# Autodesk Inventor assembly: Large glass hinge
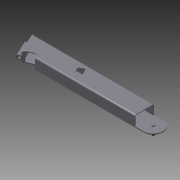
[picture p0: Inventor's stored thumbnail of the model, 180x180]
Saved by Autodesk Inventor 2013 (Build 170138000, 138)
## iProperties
Shininess: 64.0
Length Units: 11269
Angle Units: 11279
Time Units: 11290
Mass Units: 11283
Length Display Precision: 3
Angle Display Precision: 2
Compacted: True
Created: 2005-02
Part Number: Large glass hinge
Document SubType Name: Assembly
Designer: =<Author>
Manufacturer: Standard
Standards Organization: Custom
Description: =<Part Number>
Density: 0.0
Volumn: 0.0
Area: 0.0
PropertySet Name: Model Information
Control State: 0
Master: False
Checked Out: False
Checked Out Date: 2008-10-15
Last Check In Date: 2008-10-15
Author: PVitaliy
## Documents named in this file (6)
- Y:\Dropbox\Launch 2013\Eco Material Advisor\Assy, Door\_Data\Assy, Cab\Large glass hinge.iam
- Y:\Dropbox\Launch 2013\Eco Material Advisor\Assy, Door\_Data\Assy, Cab\glass sheet.ipt
- Y:\Dropbox\Launch 2013\Eco Material Advisor\Assy, Door\_Data\Assy, Cab\Glass section.ipt
- Y:\Dropbox\Launch 2013\Eco Material Advisor\Assy, Door\_Data\Assy, Cab\glass holder.ipt
- Y:\Dropbox\Launch 2013\Eco Material Advisor\Assy, Door\_Data\Assy, Cab\Hinge 1.ipt
- Y:\Dropbox\Launch 2013\Eco Material Advisor\Assy, Door\_Data\Assy, Cab\PK46.51.13.004.ipt
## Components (6 placed, 5 different names)
1. PK46.51.13.004:1 — Insert:2
2. PK46.51.13.004:2 — Insert:1
3. Glass section:1 — Mate:1, Flush:1, Flush:2, Mate:2, Mate:3
4. glass sheet:1 — Mate:1, Flush:1, Flush:2, Flush:3, Mate:4, Insert:1, Insert:2
5. glass holder:1 — Mate:2, Flush:3, Mate:3, Tangent:1, Flush:4
6. Hinge 1:1 — Tangent:1, Mate:4, Flush:4
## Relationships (11: Mate 4, Flush 4, Insert 2, Tangent 1)
- Mate:1: Glass section:1 ↔ glass sheet:1
- Flush:1: Glass section:1 ↔ glass sheet:1
- Flush:2: Glass section:1 ↔ glass sheet:1
- Mate:2: Glass section:1 ↔ glass holder:1
- Flush:3: glass sheet:1 ↔ glass holder:1
- Mate:3: Glass section:1 ↔ glass holder:1
- Tangent:1: glass holder:1 ↔ Hinge 1:1
- Mate:4: glass sheet:1 ↔ Hinge 1:1
- Flush:4: glass holder:1 ↔ Hinge 1:1
- Insert:1: PK46.51.13.004:2 ↔ glass sheet:1
- Insert:2: PK46.51.13.004:1 ↔ glass sheet:1
